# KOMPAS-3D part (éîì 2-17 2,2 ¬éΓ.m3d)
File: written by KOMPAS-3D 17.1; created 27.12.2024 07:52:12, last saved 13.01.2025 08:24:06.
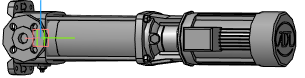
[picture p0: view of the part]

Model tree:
1. Операция без истории:4  (labels: ВМН 2-17 2,2 кВт)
